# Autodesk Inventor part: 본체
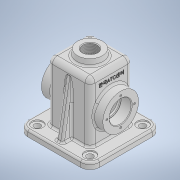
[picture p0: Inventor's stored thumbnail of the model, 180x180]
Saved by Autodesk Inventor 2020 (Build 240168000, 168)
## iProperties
Created: 2021-07
Part Number: 본체
Material: 일반
Document SubType Name: Modeling
Designer: Owner
Density: 1 g/cm^3
Appearance: 기본값
Mass: 278.26 g
Surface Area: 858.222 cm^2
Volume: 278.26 cm^3
Author: Owner
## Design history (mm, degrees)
sketch "스케치1"
  geometry: L1 (34, 34)-(-34, 34); L2 (-34, 34)-(-34, -34); L3 (-34, -34)-(34, -34); L4 (34, -34)-(34, 34); L5 (34, 34)-(-34, -34); L6 (-34, 34)-(34, -34); 1 further point
  constraints: 12 end point, 2 midpoint, 2 parallel, 1 horizontal, 1 perpendicular
  dimensions: "d0" = 68 distance of L3.end L2.end; "d1" = 68 distance of L2.end L1.end
extrude "돌출1" new body sketch "스케치1" distance "d2" = 52; taper "d3" = 0 deg
extrude "돌출2" join sketch "스케치1" distance "d4" = 53; taper "d5" = 0 deg
sketch "스케치2"
  geometry: L1 (-29, 29)-(29, 29); L2 (29, 29)-(29, -29); L3 (29, -29)-(-29, -29); L4 (-29, -29)-(-29, 29); L5 (-29, 29)-(29, -29); L6 (29, 29)-(-29, -29); 1 further point
  constraints: 12 end point, 2 midpoint, 2 parallel, 1 horizontal, 1 perpendicular
  dimensions: "d6" = 58 distance of L1.end L2.end; "d7" = 58 distance of L2.end L3.end
extrude "돌출3" cut sketch "스케치2" distance "d8" = 100; taper "d9" = 0 deg
sketch "스케치9"
  geometry: C1 r 28.5 at (34, 52); 1 further point
  constraints: 1 centre point, 1 coincident
  dimensions: "d30" = 57 diameter of C1
extrude "돌출10" join sketch "스케치9" distance "d31" = 15; taper "d32" = 0 deg
sketch "스케치10"
  geometry: C1 r 17.5 at (0, 0); 1 further point
  constraints: 1 centre point, 1 coincident
  dimensions: "d33" = 35 diameter of C1
extrude "돌출11" cut sketch "스케치10" distance "d34" = 17; taper "d35" = 0 deg
sketch "스케치11"
  geometry: C1 r 15 at (0, 0); 1 further point
  constraints: 1 centre point, 1 coincident
  dimensions: "d36" = 30 diameter of C1
extrude "돌출12" cut sketch "스케치11" extent not by distance; stored distance "d37" = 17; taper "d38" = 0 deg
sketch "스케치12"
  geometry: 2 further points
  constraints: 1 vertical alignment
  dimensions: "d39" = 22 distance of point (0, 0) point (0, 22)
hole "구멍1" sketch "스케치12" at (0, 22) diameter "d40" = 3.242; stored, may be unused: countersink angle "d44" = 90 deg, drill point angle "d46" = 118 deg; dims "d41" = 8, "d42" = 4, "d43" = 2, "d45" = 10
sketch "스케치13"
  geometry: L1 (-57, 57)-(57, 57); L2 (57, 57)-(57, -57); L3 (57, -57)-(-57, -57); L4 (-57, -57)-(-57, 57); L5 (-57, 57)-(57, -57); L6 (57, 57)-(-57, -57); L7 (-29, 29)-(29, 29) reference; L8 (-29, -29)-(-29, 29) reference; L9 (29, -29)-(-29, -29) reference; L10 (29, 29)-(29, -29) reference; 1 further point
  constraints: 12 end point, 2 midpoint, 2 parallel, 1 horizontal, 1 perpendicular
  dimensions: "d50" = 114 distance of L2.end L3.end; "d51" = 114 distance of L1.end L2.end
extrude "돌출13" join sketch "스케치13" distance "d52" = 10; taper "d53" = 0 deg
fillet "모깎기3" dims "d54" = 15
fillet "모깎기4" dims "d55" = 8
fillet "모깎기5" dims "d56" = 3
sketch "스케치14"
  geometry: L1 (-57, 42)-(-57, -42) reference; L2 (-42, -57)-(42, -57) reference; L3 (57, -42)-(57, 42) reference; L4 (42, 57)-(-42, 57) reference; L5 (-26, -34)-(26, -34) reference; L6 (-34, 26)-(-34, -26) reference; L7 (26, 34)-(-26, 34) reference; L8 (34, -26)-(34, 26) reference; A1 r 15 centre (-42, 42) between (-42, 57) and (-57, 42) reference; A2 r 15 centre (-42, -42) between (-57, -42) and (-42, -57) reference; A3 r 15 centre (42, -42) between (42, -57) and (57, -42) reference; A4 r 15 centre (42, 42) between (57, 42) and (42, 57) reference; A5 r 8 centre (26, -26) between (26, -34) and (34, -26) reference; A6 r 8 centre (-26, -26) between (-34, -26) and (-26, -34) reference; A7 r 8 centre (-26, 26) between (-26, 34) and (-34, 26) reference; A8 r 8 centre (26, 26) between (34, 26) and (26, 34) reference; 1 further point
hole "구멍2" sketch "스케치14" at (-42, -42), (42, -42), (42, 42), (-42, 42) diameter "d57" = 10; stored, may be unused: countersink angle "d61" = 90 deg, drill point angle "d63" = 118 deg; dims "d58" = 8, "d59" = 18, "d60" = 2, "d62" = 20
sketch "스케치15"
  geometry: L1 (-44, 33)-(-44, 51) reference; L2 (-42, 49)-(43.069, 34); L3 (-42, 34)-(45, 34) reference; L4 (-42, 51)-(-42, 33) reference; L5 (-52, 57)-(-42, 57) reference; 1 further point
  constraints: 2 end point, 2 point on line
  dimensions: "d64" = 8 distance from line of L5 L2.start; "d65" = 10 deg angle of L2 L3
extrude "돌출14" join sketch "스케치15" stored distance "d66" = 10; taper "d67" = 0 deg
node "작업 평면3"
sketch "스케치16"
  geometry: C1 r 20 at (0, 0); 1 further point
  constraints: 1 centre point, 1 coincident
  dimensions: "d69" = 40 diameter of C1
extrude "돌출15" join sketch "스케치16" distance "d70" = 10; taper "d71" = 8 deg
sketch "스케치17"
  geometry: C1 r 20 at (0, 0) reference; 1 further point
hole "구멍3" sketch "스케치17" at (0, 0) diameter "d72" = 22.83494; stored, may be unused: countersink angle "d76" = 90 deg, drill point angle "d78" = 118 deg; dims "d73" = 50, "d74" = 18, "d75" = 2, "d77" = 59.3
fillet "모깎기6" dims "d79" = 3
fillet "모깎기7" dims "d80" = 3
fillet "모깎기8" dims "d81" = 3
fillet "모깎기9" dims "d82" = 3
fillet "모깎기10" dims "d83" = 3
fillet "모깎기11" dims "d84" = 3
chamfer "모따기1" distance "d85" = 1; stored, may be unused: second distance "d86" = 2, angle "d87" = 45 deg
fillet "모깎기12" dims "d88" = 0.3
fillet "모깎기13" dims "d89" = 3
fillet "모깎기14" dims "d90" = 3
sketch "스케치18"
  geometry: L1 (6, 18)-(46, 18) reference; 2 further points
  constraints: 1 vertical alignment, 1 other
  dimensions: "d91" = 25 distance from line of L1 point (26, -7)
feature "엠보싱1" sketch "스케치18" dims "d92" = 0.5, "d93" = 0
fillet "모깎기15" dims "d94" = 3
node "솔리드1"
pattern_circular "원형 패턴1" dims angle "d48" = 360 deg
mirror "미러2"
mirror "미러3"
node "투영된 루프1"
node "투영된 루프2"
node "투영된 루프3"
feature "A9D066F2-1C7D-4E18-AEED-F7BC21143FA4" dims "d57" = 10, "d58" = 8, "d59" = 18, "d60" = 2, "d61" = 90 deg, "d62" = 20, "d63" = 118 deg
other parameters: "d68" = -115
